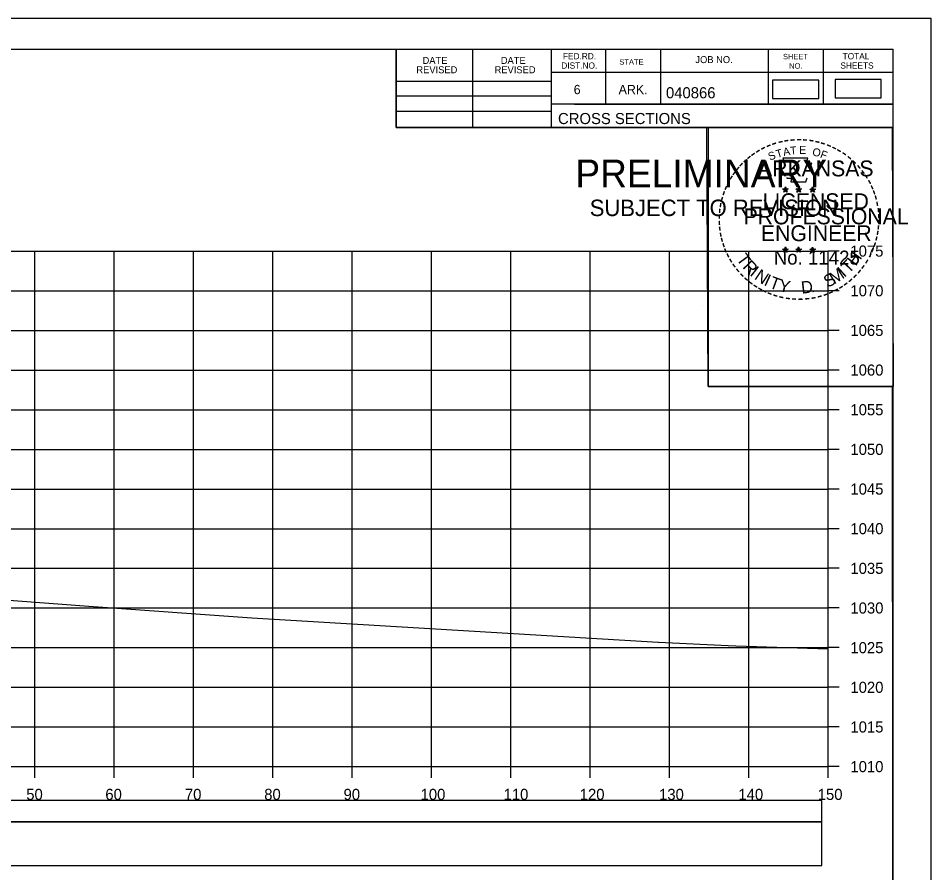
# Model space of a CAD drawing. Extents: x 1370565 to 1374448, y 301010 to 304637.
# Drawn here: x 1370782.9 to 1370898, y 301756.1 to 301863.8 of the extents above; entities that cross this region are included whole.
import ezdxf

# ---------------------------------------------------------------- set-up
doc = ezdxf.new("R2010")
doc.units = 0
for name, color, linetype in [('Default', 7, 'Continuous'), ('R_Axis', 7, 'Continuous'), ('R_Axis Annot', 7, 'Continuous'), ('R_Border', 7, 'Continuous'), ('R_Border PE', 7, 'Continuous'), ('R_Border Prem', 7, 'Continuous'), ('R_Drive', 7, 'Continuous'), ('R_Exist Surface', 7, 'Continuous'), ('R_Grid', 7, 'Continuous'), ('R_No Plot', 7, 'Continuous')]:
    doc.layers.add(name, color=color, linetype=linetype)

msp = doc.modelspace()

# ---------------------------------------------------------------- linework, layer by layer
at = {"layer": 'Default'}
msp.add_lwpolyline([(1370878.02, 301853.73), (1370883.85, 301853.73), (1370883.85, 301856.04), (1370878.02, 301856.04)], close=True, dxfattribs=at)
at = {"layer": 'R_Axis'}
for p, q in [((1370885.03, 301769.49), (1370885.03, 301834.49)), ((1370886.43, 301834.49), (1370885.03, 301834.49)), ((1370886.43, 301829.49), (1370885.03, 301829.49)), ((1370886.43, 301824.49), (1370885.03, 301824.49)), ((1370886.43, 301819.49), (1370885.03, 301819.49)), ((1370886.43, 301814.49), (1370885.03, 301814.49)), ((1370886.43, 301809.49), (1370885.03, 301809.49)), ((1370886.43, 301804.49), (1370885.03, 301804.49)), ((1370886.43, 301799.49), (1370885.03, 301799.49)), ((1370886.43, 301794.49), (1370885.03, 301794.49)), ((1370886.43, 301789.49), (1370885.03, 301789.49)), ((1370886.43, 301784.49), (1370885.03, 301784.49)), ((1370886.43, 301779.49), (1370885.03, 301779.49)), ((1370886.43, 301774.49), (1370885.03, 301774.49)), ((1370585.03, 301769.49), (1370885.03, 301769.49)), ((1370785.03, 301768.09), (1370785.03, 301769.49)), ((1370795.03, 301768.09), (1370795.03, 301769.49)), ((1370805.03, 301768.09), (1370805.03, 301769.49)), ((1370815.03, 301768.09), (1370815.03, 301769.49)), ((1370825.03, 301768.09), (1370825.03, 301769.49)), ((1370835.03, 301768.09), (1370835.03, 301769.49)), ((1370845.03, 301768.09), (1370845.03, 301769.49)), ((1370855.03, 301768.09), (1370855.03, 301769.49)), ((1370865.03, 301768.09), (1370865.03, 301769.49)), ((1370875.03, 301768.09), (1370875.03, 301769.49)), ((1370885.03, 301768.09), (1370885.03, 301769.49)), ((1370886.43, 301769.49), (1370885.03, 301769.49))]:
    msp.add_line(p, q, dxfattribs=at)
at = {"layer": 'R_Border'}
for p, q in [((1370577.03, 301859.95), (1370893.21, 301859.95)), ((1370830.57, 301850.07), (1370830.57, 301859.95)), ((1370840.25, 301850.07), (1370840.25, 301859.95)), ((1370850.11, 301859.95), (1370850.11, 301850.07)), ((1370856.95, 301859.95), (1370856.95, 301853.01)), ((1370863.89, 301859.95), (1370863.89, 301853.01)), ((1370877.47, 301859.95), (1370877.47, 301853.01)), ((1370884.41, 301859.95), (1370884.41, 301853.01)), ((1370893.21, 301654.49), (1370893.21, 301859.95)), ((1370893.21, 301857.01), (1370850.11, 301857.01)), ((1370893.21, 301857.03), (1370893.21, 301857.03)), ((1370830.57, 301855.93), (1370850.11, 301855.93)), ((1370830.57, 301854.07), (1370850.11, 301854.07)), ((1370830.57, 301852.13), (1370850.11, 301852.13)), ((1370893.21, 301853.01), (1370850.11, 301853.01)), ((1370853.07, 301853.01), (1370893.21, 301853.01)), ((1370893.21, 301850.07), (1370830.57, 301850.07))]:
    msp.add_line(p, q, dxfattribs=at)
at = {"layer": 'R_Border PE'}
for p, q in [((1370879.29, 301842.32), (1370879.64, 301842.21)), ((1370879.29, 301842.32), (1370879.54, 301842.28)), ((1370879.29, 301842.32), (1370879.53, 301842.2)), ((1370879.42, 301841.92), (1370879.64, 301842.21)), ((1370879.42, 301841.92), (1370879.55, 301842.16)), ((1370879.42, 301841.92), (1370879.64, 301842.13)), ((1370879.64, 301842.58), (1370879.6, 301842.33)), ((1370879.64, 301842.21), (1370879.64, 301842.58)), ((1370879.64, 301842.58), (1370879.69, 301842.33)), ((1370879.99, 301842.32), (1370879.64, 301842.21)), ((1370879.85, 301841.92), (1370879.64, 301842.21)), ((1370879.85, 301841.92), (1370879.64, 301842.13)), ((1370879.99, 301842.32), (1370879.7, 301842.28)), ((1370879.85, 301841.92), (1370879.72, 301842.21)), ((1370879.99, 301842.32), (1370879.78, 301842.22)), ((1370880.96, 301842.32), (1370881.31, 301842.21)), ((1370880.96, 301842.32), (1370881.21, 301842.28)), ((1370880.96, 301842.32), (1370881.2, 301842.2)), ((1370881.09, 301841.92), (1370881.31, 301842.21)), ((1370881.09, 301841.92), (1370881.22, 301842.16)), ((1370881.09, 301841.92), (1370881.31, 301842.13)), ((1370881.31, 301842.58), (1370881.27, 301842.33)), ((1370881.31, 301842.21), (1370881.31, 301842.58)), ((1370881.31, 301842.58), (1370881.36, 301842.33)), ((1370881.66, 301842.32), (1370881.31, 301842.21)), ((1370881.52, 301841.92), (1370881.31, 301842.21)), ((1370881.52, 301841.92), (1370881.31, 301842.13)), ((1370881.66, 301842.32), (1370881.37, 301842.28)), ((1370881.52, 301841.92), (1370881.39, 301842.21)), ((1370881.66, 301842.32), (1370881.45, 301842.22)), ((1370882.72, 301842.31), (1370883.07, 301842.2)), ((1370882.72, 301842.31), (1370882.98, 301842.27)), ((1370882.72, 301842.31), (1370882.96, 301842.19)), ((1370882.86, 301841.9), (1370883.07, 301842.2)), ((1370882.86, 301841.9), (1370882.98, 301842.15)), ((1370882.86, 301841.9), (1370883.07, 301842.12)), ((1370883.07, 301842.57), (1370883.03, 301842.31)), ((1370883.07, 301842.2), (1370883.07, 301842.57)), ((1370883.07, 301842.57), (1370883.12, 301842.32)), ((1370883.42, 301842.31), (1370883.07, 301842.2)), ((1370883.29, 301841.9), (1370883.07, 301842.2)), ((1370883.29, 301841.9), (1370883.07, 301842.12)), ((1370883.42, 301842.31), (1370883.13, 301842.26)), ((1370883.29, 301841.9), (1370883.15, 301842.2)), ((1370883.42, 301842.31), (1370883.22, 301842.21)), ((1370879.29, 301834.75), (1370879.64, 301834.64)), ((1370879.29, 301834.75), (1370879.54, 301834.71)), ((1370879.29, 301834.75), (1370879.52, 301834.63)), ((1370879.64, 301835.01), (1370879.59, 301834.75)), ((1370879.64, 301834.64), (1370879.64, 301835.01)), ((1370879.64, 301835.01), (1370879.68, 301834.76)), ((1370879.98, 301834.75), (1370879.64, 301834.64)), ((1370879.98, 301834.75), (1370879.7, 301834.7)), ((1370879.98, 301834.75), (1370879.78, 301834.65)), ((1370880.96, 301834.75), (1370881.3, 301834.64)), ((1370880.96, 301834.75), (1370881.21, 301834.71)), ((1370880.96, 301834.75), (1370881.19, 301834.63)), ((1370881.3, 301835.01), (1370881.26, 301834.75)), ((1370881.3, 301834.64), (1370881.3, 301835.01)), ((1370881.3, 301835.01), (1370881.35, 301834.76)), ((1370881.65, 301834.75), (1370881.3, 301834.64)), ((1370881.65, 301834.75), (1370881.37, 301834.7)), ((1370881.65, 301834.75), (1370881.45, 301834.65)), ((1370882.72, 301834.74), (1370883.07, 301834.63)), ((1370882.72, 301834.74), (1370882.98, 301834.7)), ((1370882.72, 301834.74), (1370882.96, 301834.62)), ((1370883.07, 301835), (1370883.03, 301834.74)), ((1370883.07, 301834.63), (1370883.07, 301835)), ((1370883.07, 301835), (1370883.12, 301834.75)), ((1370883.42, 301834.74), (1370883.07, 301834.63)), ((1370883.42, 301834.74), (1370883.13, 301834.69)), ((1370883.42, 301834.74), (1370883.21, 301834.64)), ((1370879.42, 301834.34), (1370879.64, 301834.64)), ((1370879.42, 301834.34), (1370879.55, 301834.59)), ((1370879.42, 301834.34), (1370879.63, 301834.56)), ((1370879.85, 301834.34), (1370879.63, 301834.56)), ((1370879.85, 301834.34), (1370879.64, 301834.64)), ((1370879.85, 301834.34), (1370879.71, 301834.63)), ((1370881.09, 301834.34), (1370881.3, 301834.64)), ((1370881.09, 301834.34), (1370881.21, 301834.59)), ((1370881.09, 301834.34), (1370881.3, 301834.56)), ((1370881.52, 301834.34), (1370881.3, 301834.64)), ((1370881.52, 301834.34), (1370881.3, 301834.56)), ((1370881.52, 301834.34), (1370881.38, 301834.63)), ((1370882.86, 301834.33), (1370883.07, 301834.63)), ((1370882.86, 301834.33), (1370882.98, 301834.58)), ((1370882.86, 301834.33), (1370883.07, 301834.55)), ((1370883.28, 301834.33), (1370883.07, 301834.63)), ((1370883.28, 301834.33), (1370883.07, 301834.55)), ((1370883.28, 301834.33), (1370883.15, 301834.62))]:
    msp.add_line(p, q, dxfattribs=at)
for points in [[(1370879.33, 301846.2), (1370879.6, 301845.38)], [(1370882.84, 301845.28), (1370882.98, 301845.56), (1370882.3, 301845.54), (1370882.45, 301846.2), (1370879.33, 301846.2)], [(1370879.82, 301843.78), (1370879.82, 301843.69), (1370880.39, 301843.67), (1370880.33, 301843.2), (1370882.2, 301843.2), (1370882.4, 301843.74)], [(1370879.64, 301842.58), (1370879.85, 301841.92), (1370879.29, 301842.32), (1370879.99, 301842.32), (1370879.42, 301841.92), (1370879.64, 301842.58)], [(1370881.31, 301842.58), (1370881.52, 301841.92), (1370880.96, 301842.32), (1370881.66, 301842.32), (1370881.09, 301841.92), (1370881.31, 301842.58)], [(1370883.07, 301842.57), (1370883.29, 301841.9), (1370882.72, 301842.31), (1370883.42, 301842.31), (1370882.86, 301841.9), (1370883.07, 301842.57)], [(1370879.64, 301835.01), (1370879.85, 301834.34), (1370879.29, 301834.75), (1370879.98, 301834.75), (1370879.42, 301834.34), (1370879.64, 301835.01)], [(1370881.3, 301835.01), (1370881.52, 301834.34), (1370880.96, 301834.75), (1370881.65, 301834.75), (1370881.09, 301834.34), (1370881.3, 301835.01)], [(1370883.07, 301835), (1370883.28, 301834.33), (1370882.72, 301834.74), (1370883.42, 301834.74), (1370882.86, 301834.33), (1370883.07, 301835)]]:
    msp.add_lwpolyline(points, dxfattribs=at)
for centre, radius in [((1370879.64, 301842.21), 0.172), ((1370879.64, 301842.21), 0.145), ((1370879.64, 301842.21), 0.116), ((1370879.64, 301842.21), 0.0991), ((1370879.64, 301842.21), 0.0747), ((1370879.64, 301842.21), 0.0495), ((1370879.64, 301842.21), 0.0296), ((1370881.31, 301842.21), 0.172), ((1370881.31, 301842.21), 0.145), ((1370881.31, 301842.21), 0.116), ((1370881.31, 301842.21), 0.0991), ((1370881.31, 301842.21), 0.0747), ((1370881.31, 301842.21), 0.0495), ((1370881.31, 301842.21), 0.0296), ((1370883.07, 301842.2), 0.172), ((1370883.07, 301842.2), 0.145), ((1370883.07, 301842.2), 0.116), ((1370883.07, 301842.2), 0.0991), ((1370883.07, 301842.2), 0.0747), ((1370883.07, 301842.2), 0.0495), ((1370883.07, 301842.2), 0.0296), ((1370879.63, 301834.64), 0.172), ((1370879.63, 301834.64), 0.145), ((1370879.63, 301834.64), 0.116), ((1370879.63, 301834.64), 0.0991), ((1370879.63, 301834.64), 0.0747), ((1370879.63, 301834.64), 0.0495), ((1370881.3, 301834.64), 0.172), ((1370881.3, 301834.64), 0.145), ((1370881.3, 301834.64), 0.116), ((1370881.3, 301834.64), 0.0991), ((1370881.3, 301834.64), 0.0747), ((1370881.3, 301834.64), 0.0495), ((1370883.07, 301834.63), 0.172), ((1370883.07, 301834.63), 0.145), ((1370883.07, 301834.63), 0.116), ((1370883.07, 301834.63), 0.0991), ((1370883.07, 301834.63), 0.0747), ((1370879.63, 301834.64), 0.0296), ((1370881.3, 301834.64), 0.0296), ((1370883.07, 301834.63), 0.0495), ((1370883.07, 301834.63), 0.0296)]:
    msp.add_circle(centre, radius, dxfattribs=at)
at = {"layer": 'R_Drive'}
for points in [[(1370885.89, 301853.8), (1370891.72, 301853.8), (1370891.72, 301856.11), (1370885.89, 301856.11)], [(1370585.82, 301762.53), (1370884.24, 301762.53), (1370884.24, 301765.23), (1370585.82, 301765.23)], [(1370585.82, 301757.01), (1370884.24, 301757.01), (1370884.24, 301762.53), (1370585.82, 301762.53)]]:
    msp.add_lwpolyline(points, close=True, dxfattribs=at)
at = {"layer": 'R_Exist Surface'}
msp.add_lwpolyline([(1370763.8, 301791.8), (1370791.83, 301789.74), (1370812.39, 301788.24), (1370863.58, 301785.17), (1370863.66, 301785.16), (1370872.43, 301784.78), (1370873.39, 301784.73), (1370885.03, 301784.35)], dxfattribs=at)
at = {"layer": 'R_Grid'}
for p, q in [((1370585.03, 301834.49), (1370885.03, 301834.49)), ((1370785.03, 301769.49), (1370785.03, 301834.49)), ((1370795.03, 301769.49), (1370795.03, 301834.49)), ((1370805.03, 301769.49), (1370805.03, 301834.49)), ((1370815.03, 301769.49), (1370815.03, 301834.49)), ((1370825.03, 301769.49), (1370825.03, 301834.49)), ((1370835.03, 301769.49), (1370835.03, 301834.49)), ((1370845.03, 301769.49), (1370845.03, 301834.49)), ((1370855.03, 301769.49), (1370855.03, 301834.49)), ((1370865.03, 301769.49), (1370865.03, 301834.49)), ((1370875.03, 301769.49), (1370875.03, 301834.49)), ((1370885.03, 301769.49), (1370885.03, 301834.49)), ((1370585.03, 301829.49), (1370885.03, 301829.49)), ((1370585.03, 301824.49), (1370885.03, 301824.49)), ((1370585.03, 301819.49), (1370885.03, 301819.49)), ((1370585.03, 301814.49), (1370885.03, 301814.49)), ((1370585.03, 301809.49), (1370885.03, 301809.49)), ((1370585.03, 301804.49), (1370885.03, 301804.49)), ((1370585.03, 301799.49), (1370885.03, 301799.49)), ((1370585.03, 301794.49), (1370885.03, 301794.49)), ((1370585.03, 301789.49), (1370885.03, 301789.49)), ((1370585.03, 301784.49), (1370885.03, 301784.49)), ((1370585.03, 301779.49), (1370885.03, 301779.49)), ((1370585.03, 301774.49), (1370885.03, 301774.49)), ((1370585.03, 301769.49), (1370885.03, 301769.49))]:
    msp.add_line(p, q, dxfattribs=at)
at = {"layer": 'R_No Plot'}
for p, q in [((1370564.63, 301863.84), (1370897.96, 301863.84)), ((1370869.24, 301827.61), (1370869.24, 301827.61))]:
    msp.add_line(p, q, dxfattribs=at)
for points in [[(1370564.62, 301863.84), (1370897.96, 301863.84), (1370897.96, 301650.51), (1370564.62, 301650.51)], [(1370810.95, 301859.95), (1370830.57, 301859.95), (1370830.57, 301850.07), (1370846.68, 301850.07), (1370869.88, 301850.07), (1370869.88, 301817.4), (1370893.09, 301817.4), (1370893.21, 301654.49), (1370577.03, 301654.49), (1370577.03, 301859.95)], [(1370869.74, 301850.07), (1370893.09, 301850.07), (1370893.23, 301817.4), (1370869.88, 301817.4)]]:
    msp.add_lwpolyline(points, close=True, dxfattribs=at)

# ---------------------------------------------------------------- texts
at = {"layer": 'R_Axis Annot'}
for s, p in [('1075', (1370887.83, 301833.79)), ('1070', (1370887.83, 301828.79)), ('1065', (1370887.83, 301823.79)), ('1060', (1370887.83, 301818.79)), ('1055', (1370887.83, 301813.79)), ('1050', (1370887.83, 301808.79)), ('1045', (1370887.83, 301803.79)), ('1040', (1370887.83, 301798.79)), ('1035', (1370887.83, 301793.79)), ('1030', (1370887.83, 301788.79)), ('1025', (1370887.83, 301783.79)), ('1020', (1370887.83, 301778.79)), ('1015', (1370887.83, 301773.79)), ('1010', (1370887.83, 301768.79)), ('50', (1370783.94, 301765.29)), ('60', (1370793.91, 301765.29)), ('70', (1370803.94, 301765.29)), ('80', (1370813.94, 301765.29)), ('90', (1370823.94, 301765.29)), ('100', (1370833.65, 301765.29)), ('110', (1370844.11, 301765.29)), ('120', (1370853.71, 301765.29)), ('130', (1370863.71, 301765.29)), ('140', (1370873.71, 301765.29)), ('150', (1370883.71, 301765.29))]:
    msp.add_text(s, height=1.4, dxfattribs=at).set_placement(p)
at = {"layer": 'R_Border'}
for s, height, p in [('DATE', 0.879, (1370833.9, 301858.09)), ('DATE', 0.879, (1370843.76, 301858.09)), ('FED.RD.', 0.782, (1370851.59, 301858.67)), ('JOB NO.', 0.879, (1370868.29, 301858.19)), ('SHEET', 0.684, (1370879.33, 301858.67)), ('TOTAL', 0.782, (1370886.85, 301858.67)), ('REVISED', 0.879, (1370833.12, 301856.91)), ('REVISED', 0.879, (1370842.98, 301856.91)), ('DIST.NO.', 0.782, (1370851.39, 301857.49)), ('STATE', 0.684, (1370858.71, 301857.99)), ('NO.', 0.684, (1370880.11, 301857.49)), ('SHEETS', 0.782, (1370886.57, 301857.49)), ('6', 1.17, (1370852.95, 301854.27)), ('ARK.', 1.172, (1370858.61, 301854.27)), ('040866', 1.4, (1370864.58, 301853.75)), ('CROSS SECTIONS', 1.4, (1370850.97, 301850.5))]:
    msp.add_text(s, height=height, rotation=360, dxfattribs=at).set_placement(p)
at = {"layer": 'R_Border PE'}
for s, height, rotation, p in [('-', 1.6, 10.2193, (1370879.51, 301847.73)), ('-', 1.6, 5.8968, (1370880.24, 301847.84)), ('-', 1.6, 0.1862, (1370881.01, 301847.91)), ('-', 1.6, 357.743, (1370881.73, 301847.9)), ('-', 1.6, 352.1617, (1370882.48, 301847.85)), ('-', 1.6, 28.7918, (1370876.81, 301846.74)), ('-', 1.6, 24.3072, (1370877.45, 301847.06)), ('-', 1.6, 19.1761, (1370878.08, 301847.33)), ('T', 1, 16.4036, (1370878.6, 301846.21)), ('-', 1.6, 13.6301, (1370878.83, 301847.57)), ('A', 1, 11.2132, (1370879.43, 301846.46)), ('T', 1, 6.0228, (1370880.28, 301846.63)), ('E', 1, 0.8323, (1370881.38, 301846.74)), ('O', 1, 350.4515, (1370882.98, 301846.53)), ('-', 1.6, 347.2049, (1370883.19, 301847.73)), ('-', 1.6, 342.3362, (1370883.83, 301847.58)), ('-', 1.6, 337.8551, (1370884.56, 301847.35)), ('-', 1.6, 334.1211, (1370885.2, 301847.08)), ('-', 1.6, 329.6409, (1370885.77, 301846.8)), ('-', 1.6, 38.9507, (1370875.16, 301845.6)), ('-', 1.6, 36.2317, (1370875.64, 301845.98)), ('-', 1.6, 34.0636, (1370876.22, 301846.37)), ('S', 1, 21.594, (1370877.69, 301845.88)), ('F', 1, 340.0707, (1370883.94, 301846.3)), ('-', 1.6, 325.8627, (1370886.42, 301846.44)), ('-', 1.6, 320.5297, (1370887.03, 301846.01)), ('-', 1.6, 50.6142, (1370873.88, 301844.22)), ('-', 1.6, 48.423, (1370874.28, 301844.71)), ('-', 1.6, 42.9622, (1370874.73, 301845.18)), ('ARKANSAS', 2, 360, (1370876.18, 301843.91)), ('-', 1.6, 315.5786, (1370887.63, 301845.52)), ('-', 1.6, 309.8797, (1370888.2, 301844.97)), ('-', 1.6, 58.0706, (1370873.14, 301843.13)), ('-', 1.6, 54.2325, (1370873.46, 301843.65)), ('-', 1.6, 306.6522, (1370888.72, 301844.37)), ('-', 1.4, 303.6753, (1370889.21, 301843.8)), ('-', 1.6, 67.7743, (1370872.57, 301841.9)), ('-', 1.6, 62.8713, (1370872.83, 301842.51)), ('-', 1.6, 299.6684, (1370889.53, 301843.2)), ('-', 1.6, 294.6628, (1370889.85, 301842.59)), ('-', 1.6, 72.3945, (1370872.35, 301841.27)), ('LICENSED', 2, 360, (1370876.78, 301839.77)), ('DWB', 0.01, 360, (1370879.63, 301842.21)), ('DWB', 0.01, 360, (1370881.3, 301842.21)), ('DWB', 0.01, 360, (1370883.06, 301842.2)), ('-', 1.6, 290.5728, (1370890.11, 301842.01)), ('-', 1.6, 81.2013, (1370872.02, 301839.84)), ('-', 1.6, 75.461, (1370872.15, 301840.56)), ('-', 1.6, 285.1233, (1370890.34, 301841.43)), ('-', 1.6, 280.5493, (1370890.54, 301840.69)), ('-', 1.6, 85.1863, (1370871.94, 301839.15)), ('PROFESSIONAL', 2, 360, (1370874.36, 301837.86)), ('-', 1.6, 276.5962, (1370890.7, 301839.92)), ('-', 1.6, 94.1959, (1370871.95, 301837.73)), ('-', 1.6, 89.0622, (1370871.92, 301838.45)), ('-', 1.6, 274.3301, (1370890.76, 301839.2)), ('-', 1.6, 269.9407, (1370890.8, 301838.56)), ('-', 1.6, 98.9479, (1370872.03, 301837.06)), ('ENGINEER', 2, 360, (1370876.55, 301835.74)), ('-', 1.6, 260.9953, (1370890.71, 301837.24)), ('-', 1.6, 263.5172, (1370890.78, 301837.9)), ('-', 1.6, 101.7149, (1370872.16, 301836.33)), ('-', 1.6, 105.4578, (1370872.32, 301835.73)), ('-', 1.6, 255.7626, (1370890.6, 301836.57)), ('-', 1.6, 109.0874, (1370872.54, 301835.1)), ('-', 1.6, 114.0643, (1370872.79, 301834.5)), ('-', 1.6, 247.8887, (1370890.19, 301835.17)), ('-', 1.6, 252.8681, (1370890.42, 301835.85)), ('-', 1.6, 115.7289, (1370873.1, 301833.89)), ('-', 1.6, 120.4471, (1370873.45, 301833.3)), ('T', 1.54, 306.0406, (1370873.4, 301833.48)), ('No. 11425', 1.757, 360, (1370878.17, 301832.79)), ('DWB', 0.01, 360, (1370879.62, 301834.64)), ('DWB', 0.01, 360, (1370881.29, 301834.64)), ('DWB', 0.01, 360, (1370883.06, 301834.63)), ('H', 1.54, 54.6088, (1370888.52, 301832.51)), ('-', 1.6, 244.6197, (1370889.93, 301834.54)), ('-', 1.6, 125.8934, (1370873.86, 301832.74)), ('R', 1.54, 314.005, (1370874.16, 301832.43)), ('I', 1.54, 321.9694, (1370875.06, 301831.5)), ('I', 1.54, 42.1136, (1370887.06, 301831.09)), ('T', 1.54, 46.6444, (1370887.63, 301831.57)), ('-', 1.6, 233.8452, (1370889.13, 301833.14)), ('-', 1.6, 239.0712, (1370889.54, 301833.79)), ('-', 1.6, 130.7181, (1370874.32, 301832.19)), ('-', 1.6, 134.2238, (1370874.84, 301831.64)), ('N', 1.54, 326.5002, (1370875.63, 301831.03)), ('I', 1.54, 335.3603, (1370876.83, 301830.24)), ('T', 1.54, 339.8912, (1370877.49, 301829.91)), ('S', 1.54, 26.9312, (1370884.94, 301829.84)), ('M', 1.54, 32.6563, (1370885.78, 301830.25)), ('-', 1.6, 225.7653, (1370888.23, 301832.01)), ('-', 1.6, 231.2538, (1370888.7, 301832.57)), ('-', 1.6, 138.9338, (1370875.36, 301831.18)), ('-', 1.6, 144.6463, (1370875.92, 301830.77)), ('-', 1.6, 148.0898, (1370876.48, 301830.4)), ('Y', 1.54, 347.8556, (1370878.71, 301829.47)), ('D', 1.54, 6.3969, (1370881.7, 301829.11)), ('-', 1.6, 212.2491, (1370886.62, 301830.64)), ('-', 1.6, 215.7363, (1370887.15, 301831.03)), ('-', 1.6, 221.0851, (1370887.7, 301831.5)), ('-', 1.6, 151.5704, (1370877.06, 301830.08)), ('-', 1.6, 154.6002, (1370877.58, 301829.83)), ('-', 1.6, 158.5612, (1370878.2, 301829.58)), ('-', 1.6, 162.7983, (1370878.89, 301829.36)), ('.', 1.54, 13.7642, (1370882.89, 301829.24)), ('-', 1.6, 200.7184, (1370884.82, 301829.7)), ('-', 1.6, 204.2516, (1370885.44, 301829.98)), ('-', 1.6, 207.3568, (1370886.06, 301830.3)), ('-', 1.6, 167.5555, (1370879.6, 301829.2)), ('-', 1.6, 173.1155, (1370880.38, 301829.09)), ('-', 1.6, 176.5183, (1370881.12, 301829.04)), ('-', 1.6, 181.5918, (1370881.87, 301829.05)), ('-', 1.6, 185.8167, (1370882.68, 301829.13)), ('-', 1.6, 191.2858, (1370883.41, 301829.26)), ('-', 1.6, 195.4743, (1370884.14, 301829.46))]:
    msp.add_text(s, height=height, rotation=rotation, dxfattribs=at).set_placement(p)
at = {"layer": 'R_Border Prem'}
for s, height, p in [('PRELIMINARY', 3.5, (1370853.16, 301842.53)), ('DWB', 0.01, (1370853.9, 301844.38)), ('SUBJECT TO REVISION', 2.0751, (1370854.97, 301838.9))]:
    msp.add_text(s, height=height, rotation=360, dxfattribs=at).set_placement(p)

doc.saveas('drawing.dxf')
